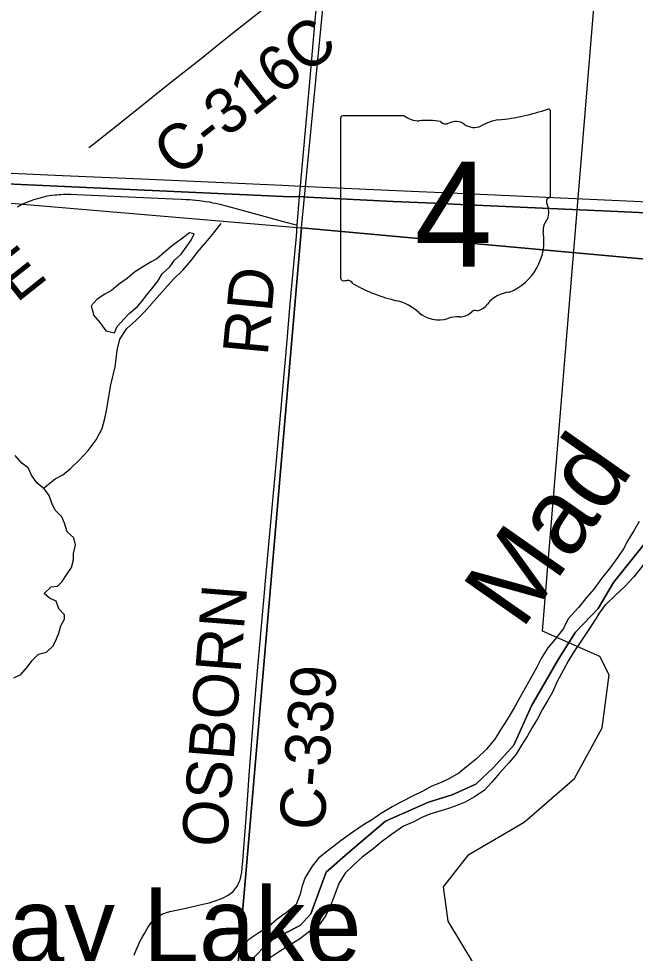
# Model space of a CAD drawing. Extents: x 0 to 1134, y 0 to 440.
# Drawn here: x 199.03 to 222.27, y 86.55 to 121.74 of the extents above; entities that cross this region are included whole.
import ezdxf

# ---------------------------------------------------------------- set-up
doc = ezdxf.new("R2010")
doc.units = 0
for name, color, linetype in [('Default', 7, 'Continuous'), ('GM_X_County_Road', 7, 'Continuous'), ('GM_X_County_Road_Text', 7, 'Continuous'), ('GM_X_Interstate_Route', 7, 'Continuous'), ('GM_X_Major_River', 7, 'Continuous'), ('GM_X_Major_River_Text', 7, 'Continuous'), ('GM_X_Minor_Lake', 7, 'Continuous'), ('GM_X_Minor_Lake_Text', 7, 'Continuous'), ('GM_X_Minor_River', 7, 'Continuous'), ('GM_X_Rail_Line', 7, 'Continuous'), ('GM_X_Section', 7, 'Continuous'), ('GM_X_State_Route', 7, 'Continuous'), ('GM_X_State_Shield', 7, 'Continuous'), ('GM_X_Township', 7, 'Continuous')]:
    doc.layers.add(name, color=color, linetype=linetype)

msp = doc.modelspace()

# ---------------------------------------------------------------- linework, layer by layer
at = {"layer": 'Default'}
for points in [[(185.809, 116.536), (188.153, 116.432), (190.835, 116.285), (196.688, 116.012), (197.628, 115.969), (200.691, 115.832), (203.671, 115.705), (208.978, 115.467), (209.655, 115.436), (209.945, 115.423)], [(225.08, 114.314), (221.597, 114.473), (219.045, 114.59), (215.417, 114.758), (214.999, 114.776), (213.147, 114.854), (209.918, 115.02), (209.619, 115.036), (209.274, 115.034), (205.708, 115.196), (194.17, 115.719)], [(209.945, 115.423), (210.467, 115.399), (213.26, 115.271), (216.146, 115.139), (223.873, 114.788), (227.412, 114.636), (230.869, 114.48), (230.929, 114.477), (231.508, 114.451), (235.698, 114.261), (240.26, 114.054), (242.494, 113.955), (243.799, 113.906), (244.918, 113.884), (246.131, 113.883), (247.343, 113.903), (248.555, 113.946), (254.234, 114.198), (255.66, 114.266)]]:
    msp.add_lwpolyline(points, dxfattribs=at)
at = {"layer": 'GM_X_County_Road'}
for points in [[(201.679, 116.881), (201.811, 116.981), (202.417, 117.464), (203.291, 118.16), (204.822, 119.379), (205.844, 120.19), (206.719, 120.886), (207.447, 121.468), (208.544, 122.334), (209.709, 123.264), (210.221, 123.669), (210.396, 123.806)], [(210.107, 120.508), (210.207, 121.675), (210.228, 121.927), (210.265, 122.368), (210.302, 122.852), (210.319, 123.096), (210.334, 123.352), (210.357, 123.585), (210.368, 123.662), (210.396, 123.806)], [(209.532, 113.964), (209.619, 115.036), (209.655, 115.436), (209.743, 116.428), (209.991, 119.209), (210.107, 120.508)], [(198.989, 114.652), (199.102, 114.713), (199.195, 114.76), (199.293, 114.805), (199.384, 114.843), (199.482, 114.881), (199.609, 114.926), (199.703, 114.957), (199.795, 114.985), (199.934, 115.022), (200.03, 115.045), (200.103, 115.061), (200.193, 115.077), (200.281, 115.09), (200.41, 115.104), (200.474, 115.109), (200.548, 115.115), (200.617, 115.12), (200.707, 115.125), (200.831, 115.126), (201.005, 115.126), (201.229, 115.116), (204.843, 114.959), (205.168, 114.942), (205.342, 114.934), (205.467, 114.924), (205.581, 114.915), (205.708, 114.902), (205.848, 114.886), (205.995, 114.865), (206.09, 114.853), (206.209, 114.835), (206.351, 114.806), (206.453, 114.787), (206.616, 114.75), (206.989, 114.657), (208.966, 114.112), (209.532, 113.964)], [(209.16, 109.773), (209.256, 110.863), (209.465, 113.154), (209.497, 113.529), (209.532, 113.964)], [(203.391, 86.486), (203.429, 86.579), (203.501, 86.755), (203.551, 86.874), (203.605, 86.997), (203.696, 87.166), (203.771, 87.294), (203.904, 87.521), (203.985, 87.642), (204.052, 87.736), (204.128, 87.816), (204.196, 87.879), (204.263, 87.927), (204.348, 87.978), (204.43, 88.021), (204.504, 88.053), (204.601, 88.09), (204.731, 88.124), (204.857, 88.151), (204.977, 88.18), (205.495, 88.291), (205.812, 88.363), (206.042, 88.415), (206.224, 88.457), (206.325, 88.487), (206.481, 88.537), (206.612, 88.583), (206.711, 88.623), (206.81, 88.671), (206.927, 88.737), (207.02, 88.806), (207.118, 88.881), (207.196, 88.972), (207.254, 89.054), (207.302, 89.139), (207.348, 89.241), (207.377, 89.321), (207.403, 89.424), (207.438, 89.61), (207.46, 89.774), (207.48, 90.035), (207.591, 91.47), (207.665, 92.51), (207.718, 93.253), (207.881, 95.376), (207.991, 96.76), (208.229, 99.431), (208.28, 99.985), (208.331, 100.571), (208.748, 105.109), (209.133, 109.471), (209.16, 109.773)]]:
    msp.add_lwpolyline(points, dxfattribs=at)
at = {"layer": 'GM_X_Interstate_Route'}
for points in [[(178.48, 116.86), (180.078, 116.79), (183.141, 116.655), (185.183, 116.564), (185.809, 116.536), (188.153, 116.432), (190.835, 116.285), (196.688, 116.012), (197.628, 115.969), (200.691, 115.832), (203.671, 115.705), (208.978, 115.467), (209.655, 115.436), (209.945, 115.423)], [(193.722, 115.735), (194.17, 115.719), (205.708, 115.196)], [(209.945, 115.423), (210.467, 115.399), (213.26, 115.271), (216.146, 115.139), (223.873, 114.788), (227.412, 114.636), (230.869, 114.48), (230.929, 114.477), (231.508, 114.451), (235.698, 114.261), (240.26, 114.054), (242.494, 113.955), (243.799, 113.906), (244.918, 113.884), (246.131, 113.883), (247.343, 113.903), (248.555, 113.946), (254.234, 114.198), (255.66, 114.266)], [(205.708, 115.196), (209.274, 115.034), (209.619, 115.036), (209.918, 115.02)], [(209.918, 115.02), (213.147, 114.854), (214.999, 114.776)], [(214.999, 114.776), (215.417, 114.758), (219.045, 114.59), (221.597, 114.473)], [(221.597, 114.473), (225.08, 114.314), (226.942, 114.229), (229.548, 114.106), (230.252, 114.076), (230.888, 114.05), (231.006, 114.045), (232.714, 113.975), (236.587, 113.798)]]:
    msp.add_lwpolyline(points, dxfattribs=at)
at = {"layer": 'GM_X_Major_River'}
msp.add_line((220.886, 99.302), (221.155, 99.676), dxfattribs=at)
for points in [[(222.408, 102.801), (222.229, 102.486), (221.98, 102.094), (221.824, 101.779), (221.611, 101.465), (221.304, 101.051), (220.998, 100.66), (220.703, 100.257), (220.445, 99.956), (220.127, 99.565), (219.741, 99.142), (219.561, 98.782), (219.254, 98.38), (218.972, 98.045), (218.723, 97.652), (218.555, 97.326), (218.352, 96.955), (218.126, 96.562), (217.899, 96.158), (217.708, 95.798), (217.434, 95.349), (217.185, 94.968), (216.971, 94.609), (216.665, 94.24), (216.28, 93.874), (215.908, 93.565), (215.617, 93.333), (215.236, 93.114), (214.948, 92.985), (214.603, 92.845), (214.268, 92.66), (213.898, 92.476), (213.437, 92.237), (213.113, 92.063), (212.663, 91.801), (212.372, 91.592), (212.025, 91.384), (211.62, 91.109)], [(222.584, 101.201), (222.207, 100.721), (221.867, 100.365), (221.517, 100.032), (221.155, 99.676)], [(220.886, 99.302), (220.516, 98.735), (220.185, 98.254), (219.924, 97.861), (219.734, 97.547), (219.315, 96.76), (219.146, 96.388), (218.955, 96.051), (218.776, 95.737), (218.585, 95.377), (218.383, 95.052), (218.204, 94.737), (217.979, 94.39), (217.777, 94.053), (217.518, 93.74), (217.143, 93.317), (216.861, 92.994), (216.569, 92.682), (216.209, 92.44), (215.851, 92.244), (215.483, 92.094), (215.196, 91.987), (214.817, 91.883), (214.53, 91.788), (214.219, 91.659), (213.919, 91.495), (213.539, 91.334), (213.087, 91.026), (212.692, 90.729), (212.378, 90.475), (211.972, 90.166), (211.657, 89.878), (211.341, 89.567), (211.092, 89.185), (210.908, 88.666), (210.774, 88.316), (210.606, 87.978), (210.357, 87.62), (209.998, 87.367), (209.615, 87.081), (209.198, 86.829), (208.828, 86.599), (208.527, 86.39)], [(211.62, 91.109), (211.191, 90.801), (210.749, 90.459), (210.331, 90.128), (210.095, 89.826), (209.823, 89.411), (209.712, 89.095), (209.635, 88.778), (209.489, 88.383), (209.163, 88.106), (208.78, 87.831), (208.454, 87.566), (208.084, 87.324), (207.701, 87.072), (207.281, 86.672), (206.885, 86.329), (206.535, 85.996), (206.182, 85.549), (205.954, 85.088), (205.83, 84.692), (205.683, 84.32), (205.458, 83.961), (205.17, 83.832), (204.501, 83.355)]]:
    msp.add_lwpolyline(points, dxfattribs=at)
at = {"layer": 'GM_X_Minor_Lake'}
for points in [[(205.032, 112.76), (205.152, 112.872), (205.349, 113.131), (205.535, 113.402), (205.652, 113.639), (205.471, 113.676), (205.206, 113.474), (204.965, 113.296), (204.77, 113.15), (204.493, 112.915), (204.24, 112.691), (204.022, 112.58), (203.735, 112.402), (203.402, 112.19), (203.126, 111.955), (202.793, 111.732), (202.528, 111.508), (202.287, 111.364), (201.989, 111.174), (201.769, 110.927), (201.823, 110.698)], [(201.823, 110.698), (201.855, 110.573), (202.09, 110.296), (202.324, 109.985), (202.642, 109.913), (202.747, 110.15), (203.013, 110.431), (203.198, 110.634), (203.509, 110.902), (203.659, 111.082), (203.879, 111.353), (204.088, 111.612), (204.273, 111.859), (204.436, 112.13), (204.725, 112.4), (204.91, 112.647), (205.032, 112.76)], [(198.85, 96.919), (199.113, 97.052), (199.368, 97.333), (199.542, 97.57), (199.784, 97.817), (200.081, 97.892), (200.334, 98.128), (200.463, 98.388), (200.546, 98.603), (200.618, 98.875), (200.758, 99.124), (200.761, 99.294), (200.548, 99.525), (200.45, 99.811), (200.201, 99.917), (199.999, 100.102), (200.264, 100.349), (200.503, 100.368), (200.676, 100.548), (200.839, 100.796), (201.025, 101.078), (201.097, 101.362), (201.101, 101.601), (201.174, 101.93), (201.109, 102.193), (200.862, 102.424), (200.765, 102.744), (200.666, 102.984), (200.408, 103.238), (200.286, 103.491), (200.188, 103.788), (200.01, 104.03), (199.717, 104.261), (199.517, 104.549), (199.395, 104.824), (199.148, 105.009), (198.902, 105.297)]]:
    msp.add_lwpolyline(points, dxfattribs=at)
at = {"layer": 'GM_X_Minor_River'}
msp.add_lwpolyline([(199.967, 104.064), (200.413, 104.411), (200.7, 104.566), (200.987, 104.801), (201.322, 105.127), (201.657, 105.475), (201.958, 105.881), (202.181, 106.31), (202.277, 106.685), (202.338, 106.98), (202.388, 107.275), (202.438, 107.582), (202.511, 107.956), (202.596, 108.32), (202.669, 108.626), (202.707, 108.933), (202.746, 109.251), (202.843, 109.671), (203.11, 110.077), (203.445, 110.38), (203.779, 110.705), (204.149, 111.121), (204.542, 111.56), (204.866, 111.931), (205.235, 112.279), (205.547, 112.639), (205.756, 112.932), (206.08, 113.314), (206.334, 113.607), (206.67, 114.023)], dxfattribs=at)
at = {"layer": 'GM_X_Rail_Line'}
msp.add_lwpolyline([(218.648, 83.037), (217.883, 83.933), (216.691, 85.332), (215.218, 87.758), (215.044, 89.058), (215.997, 90.271), (218.076, 91.484), (219.982, 93.131), (221.022, 95.038), (221.282, 97.031), (220.935, 97.724), (218.769, 98.677), (221.544, 132.36), (223.618, 133.946), (235.537, 142.526)], dxfattribs=at)
at = {"layer": 'GM_X_Section'}
for points in [[(212.603, 143.785), (241.786, 141.042), (242.613, 140.903), (239.744, 111.129), (209.686, 113.866)], [(209.686, 113.866), (207.062, 83.429), (175.637, 86.374), (175.645, 86.452), (178.478, 116.514)], [(239.744, 111.129), (236.861, 80.551), (207.062, 83.429), (209.686, 113.866)]]:
    msp.add_lwpolyline(points, close=True, dxfattribs=at)
at = {"layer": 'GM_X_State_Route'}
for points in [[(193.722, 115.735), (194.17, 115.719), (205.708, 115.196)], [(205.708, 115.196), (209.274, 115.034), (209.619, 115.036), (209.918, 115.02)], [(209.918, 115.02), (213.147, 114.854), (214.999, 114.776)], [(214.999, 114.776), (215.417, 114.758), (219.045, 114.59), (221.597, 114.473)], [(221.597, 114.473), (225.08, 114.314), (226.942, 114.229), (229.548, 114.106), (230.252, 114.076), (230.888, 114.05), (231.006, 114.045), (232.714, 113.975), (236.587, 113.798)]]:
    msp.add_lwpolyline(points, dxfattribs=at)
at = {"layer": 'GM_X_State_Shield'}
for p, q in [((219.075, 115.093), (219.075, 118.234)), ((211.165, 117.982), (211.165, 111.978)), ((213.56, 118.085), (211.243, 118.085)), ((219.074, 115.094), (219.075, 115.093))]:
    msp.add_line(p, q, dxfattribs=at)
for centre, radius, start, end in [((216.258, 126.27), 8.388, 275.8445, 288.9065), ((218.988, 118.247), 0.0881, 351.8621, 97.738), ((211.256, 117.994), 0.0916, 98.1301, 188.1301), ((214.111, 118.782), 0.889, 231.6195, 271.1119), ((214.406, 114.714), 3.191, 80.4867, 94.9883), ((217.328, 116.251), 1.688, 97.3462, 120.7689), ((215.13, 118.026), 0.256, 219.7921, 297.1024), ((215.507, 117.332), 0.533, 54.4667, 119.1411), ((216.195, 118.283), 0.641, 233.8562, 294.8282), ((218.981, 115.081), 0.0942, 289.6038, 7.7341), ((219.055, 114.863), 0.136, 107.944, 210.337), ((218.188, 114.466), 0.818, 340.033, 23.6496), ((219.391, 113.779), 0.595, 136.8065, 186.9296), ((216.728, 113.379), 2.098, 292.3089, 8.9858), ((211.257, 111.965), 0.0925, 171.9584, 258.3066), ((211.271, 112.579), 0.706, 267.339, 280.6039), ((211.415, 111.632), 0.254, 29.7484, 93.2717), ((214.627, 117.026), 6.058, 240.4129, 257.1985), ((217.612, 110.293), 1.149, 94.4031, 142.5768), ((212.821, 109.281), 1.895, 47.1842, 75.836), ((216.156, 111.396), 0.678, 282.8732, 323.2771), ((214.871, 111.602), 1.203, 230.7004, 286.2918), ((215.566, 109.526), 0.988, 85.6951, 111.2099), ((215.654, 111.152), 0.641, 268.777, 315.5493), ((216.233, 110.571), 0.18, 65.7517, 132.6484)]:
    msp.add_arc(centre, radius, start, end, dxfattribs=at)
at = {"layer": 'GM_X_Township'}
for points in [[(207.765, 86.254), (208.481, 87.014), (209.643, 87.595), (210.045, 88.042), (210.626, 89.606), (211.431, 90.321), (212.861, 91.528), (214.471, 92.243), (215.365, 92.512), (216.259, 92.914), (216.929, 93.54), (217.689, 94.389), (218.36, 95.864), (219.388, 97.652), (220.014, 98.635), (220.863, 99.529), (221.444, 100.513), (222.696, 102.077)], [(222.696, 102.077), (221.444, 100.513), (220.863, 99.529), (220.014, 98.635), (219.388, 97.652), (218.36, 95.864), (217.689, 94.389), (216.929, 93.54), (216.259, 92.914), (215.365, 92.512), (214.471, 92.243), (212.861, 91.528), (211.431, 90.321), (210.626, 89.606), (210.045, 88.042), (209.643, 87.595), (208.481, 87.014), (207.765, 86.254)]]:
    msp.add_lwpolyline(points, dxfattribs=at)

# ---------------------------------------------------------------- texts
at = {"layer": 'GM_X_County_Road_Text'}
for s, height, rotation, p in [('C-316C', 1.7045, 38.4769, (204.991, 115.735)), ('E', 1.705, 38.3713, (198.956, 111.016)), ('RD', 1.7045, 84.6295, (208.414, 109.019)), ('OSBORN', 1.7045, 85.4325, (206.863, 90.503)), ('C-339', 1.7045, 85.377, (210.535, 91.136))]:
    msp.add_text(s, height=height, rotation=rotation, dxfattribs=at).set_placement(p)
at = {"layer": 'GM_X_Major_River_Text'}
msp.add_text('Mad', height=2.8403, rotation=54.9982, dxfattribs=at).set_placement((217.985, 98.688))
at = {"layer": 'GM_X_Minor_Lake_Text'}
msp.add_text('Medway Lake', height=2.84082, rotation=0.0032, dxfattribs=at).set_placement((188.515, 86.187))
at = {"layer": 'GM_X_State_Shield'}
msp.add_text('4', height=3.955, dxfattribs=at).set_placement((213.945, 112.401))

doc.saveas('drawing.dxf')
